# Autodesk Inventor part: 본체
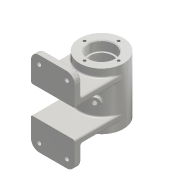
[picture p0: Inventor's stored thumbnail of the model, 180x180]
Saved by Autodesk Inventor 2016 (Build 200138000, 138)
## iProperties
Created: 2017-02
Part Number: 본체
Material: 알루미늄 6061
Document SubType Name: Modeling
Designer: H
Density: 2.7 g/cm^3
Appearance: 알루미늄 - 평지
Mass: 354.506 g
Surface Area: 423.343 cm^2
Volume: 131.299 cm^3
Author: H
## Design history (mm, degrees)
sketch "스케치1"
  geometry: L1 (0, 0)-(0, -48.036); L2 (0, 0)-(27, 0); L3 (27, 35)-(0, 35); L4 (0, 35)-(0, -35); L5 (0, -35)-(27, -35); L6 (27, -35)-(27, 35); L7 (0, -10)-(27, -10); L8 (32, -5)-(21.317, -5); L9 (21.317, -5)-(21.317, -10); L10 (21.317, -10)-(32, -10); L11 (32, -10)-(32, -5)
  constraints: 22 end point, 4 horizontal, 4 parallel, 4 point on line, 2 perpendicular, 1 vertical, 1 other
  dimensions: "d0" = 54 diameter of L6 L1; "d1" = 48.03642 distance of L1.start L1.end; "d2" = 27 distance of L1.start L2.end; "d4" = 70 distance of L5.end L3.start; "d5" = 5 distance of L10.end L8.start; "d6" = 10.68275 distance of L8.start L8.end; "d7" = 5 distance between parallel lines of L6 L11; "d109" = 25 distance between parallel lines of L5 L10
revolve "회전1" stored, may be unused: angle "d8" = 90 deg
revolve "회전2" stored, may be unused: angle "d9" = 90 deg
sketch "스케치2"
  geometry: L1 (-52, 52)-(-60, 52); L2 (-60, 52)-(-60, 17); L3 (-60, 17)-(-52, 17); L4 (-52, 17)-(-52, 52); L5 (0, 0)-(-22.662, 0); L6 (-52, 17)-(-2, 17); L7 (-2, 17)-(-2, 25); L8 (-2, 25)-(-52, 25); L9 (-52, 25)-(-52, 17)
  constraints: 18 end point, 4 parallel, 3 horizontal, 2 perpendicular
  dimensions: "d10" = 22.66207 distance of L5.start L5.end; "d11" = 52 distance between parallel lines of L5 L1; "d12" = 8 distance of L1.start L1.end; "d13" = 17 distance between parallel lines of L5 L3; "d14" = 60 distance from line of L5.start L2; "d15" = 50 distance of L7.end L8.end; "d16" = 8 distance of L6.end L7.end
extrude "돌출1" join sketch "스케치2" stored distance "d17" = 54; taper "d18" = 0 deg
sketch "스케치3"
  geometry: 2 further points
  constraints: 1 coincident
hole "구멍1" sketch "스케치3" at (0, 0) diameter "d19" = 32; stored, may be unused: countersink angle "d23" = 90 deg, drill point angle "d25" = 0 deg; dims "d20" = 6, "d21" = 4, "d22" = 2, "d24" = 12
sketch "스케치4"
  geometry: 2 further points
  constraints: 1 coincident
hole "구멍2" sketch "스케치4" at (0, 0) diameter "d26" = 28; stored, may be unused: countersink angle "d30" = 90 deg, drill point angle "d32" = 0 deg; dims "d27" = 6, "d28" = 4, "d29" = 2, "d31" = 3
sketch "스케치5"
  geometry: 2 further points
  constraints: 1 coincident
hole "구멍3" sketch "스케치5" at (0, 0) diameter "d33" = 44; stored, may be unused: countersink angle "d37" = 90 deg, drill point angle "d39" = 0 deg; dims "d34" = 6, "d35" = 4, "d36" = 2, "d38" = 40
sketch "스케치6"
  geometry: C1 r 5 at (0, 0) reference; 2 further points
  constraints: 1 coincident
hole "구멍4" sketch "스케치6" at (0, 0) diameter "d40" = 5.188; stored, may be unused: countersink angle "d44" = 90 deg, drill point angle "d46" = 0 deg; dims "d41" = 12, "d42" = 4, "d43" = 2, "d45" = 23.25
sketch "스케치8" dims "d47" = 9
  geometry: L1 (14.5, 14.402)-(10, 11.804); L2 (10, 11.804)-(5.5, 14.402); L3 (5.5, 14.402)-(5.5, 19.598); L4 (5.5, 19.598)-(10, 22.196); L5 (10, 22.196)-(14.5, 19.598); L6 (14.5, 19.598)-(14.5, 14.402); L7 (0, -8)-(0, 27) reference; 4 further points
  constraints: 12 end point, 1 coincident, 1 horizontal alignment, 1 midpoint, 1 parallel, 15 other
  dimensions: "d48" = 17 horizontal distance of point (10, 17) point (27, -25); "d49" = 42 vertical distance of point (27, -25) point (10, 17)
extrude "돌출2" cut sketch "스케치8" distance "d50" = 3; taper "d51" = 0 deg
sketch "스케치9"
  geometry: 2 further points
  dimensions: "d52" = 42 vertical distance of point (10, 17) point (27, -25); "d53" = 17 horizontal distance of point (27, -25) point (10, 17)
hole "구멍5" sketch "스케치9" at (10, 17) diameter "d54" = 5; stored, may be unused: countersink angle "d58" = 90 deg, drill point angle "d60" = 0 deg; dims "d55" = 12, "d56" = 4, "d57" = 2, "d59" = 23.25
sketch "스케치10"
  geometry: L1 (5, 32)-(-5, 32) reference; L2 (0, 0)-(0, 32); 1 further point
  constraints: 2 end point, 1 midpoint, 1 point on line
  dimensions: "d67" = 21 distance of L2.start point (0, 21)
hole "구멍6" sketch "스케치10" at (0, 21) diameter "d68" = 3.459; stored, may be unused: countersink angle "d72" = 90 deg, drill point angle "d74" = 118 deg; dims "d69" = 8, "d70" = 4, "d71" = 2, "d73" = 10
fillet "모깎기2" dims "d79" = 10
fillet "모깎기3" dims "d80" = 2
fillet "모깎기4" dims "d81" = 2
fillet "모깎기5" dims "d82" = 2
fillet "모깎기6" dims "d83" = 2
fillet "모깎기7" dims "d84" = 2
fillet "모깎기8" dims "d85" = 2
fillet "모깎기9" dims "d86" = 2
chamfer "모따기1" distance "d87" = 1; stored, may be unused: second distance "d88" = 2, angle "d89" = 45 deg
fillet "모깎기10" dims "d90" = 0.3
fillet "모깎기11" dims "d91" = 3
sketch "스케치11"
  geometry: L1 (0, 0)-(14.705, -22.644); L2 (0, 0)-(0, -27); L3 (12.458, -19.184)-(16.339, -25.16); L4 (16.339, -25.16)-(21.371, -21.892); L5 (21.371, -21.892)-(17.49, -15.916); L6 (17.49, -15.916)-(12.458, -19.184); A1 r 27 centre (0, 0) between (-23.276, -13.683) and (23.276, -13.683) reference; 1 further point
  constraints: 12 end point, 2 parallel, 2 point on circle, 2 point on line, 1 perpendicular
  dimensions: "d92" = 33 deg angle of L2 L1; "d93" = 30 distance from line of point (0, 0) L4; "d94" = 6 distance from line of L3 L4.end; "d95" = 5.97589 vertical distance of L4.end L5.end
revolve "회전3" sketch "스케치11" stored, may be unused: angle "d96" = 90 deg
sketch "스케치13"
  geometry: 2 further points
  constraints: 1 coincident
hole "구멍7" sketch "스케치13" at (0, 0) diameter "d97" = 5.188; stored, may be unused: countersink angle "d101" = 90 deg, drill point angle "d103" = 118 deg; dims "d98" = 17.5, "d99" = 4, "d100" = 2, "d102" = 17.5
fillet "모깎기12" dims "d104" = 2
node "작업 평면2"
sketch "스케치14"
  geometry: L1 (0, 57.5)-(0, -12.5) reference; L2 (54, -19.5)-(54, -4.5) reference; L3 (60, -19.5)-(54, -19.5) reference; L4 (60, 3.5)-(60, -19.5) reference; L5 (2, 3.5)-(60, 3.5) reference; L6 (2, -0.5)-(2, 3.5) reference; L7 (50, -0.5)-(2, -0.5) reference; L8 (50, 45.5)-(2, 45.5) reference; L9 (2, 41.5)-(2, 45.5) reference; L10 (2, 41.5)-(60, 41.5) reference; L11 (60, 64.5)-(60, 41.5) reference; L12 (60, 64.5)-(54, 64.5) reference; L13 (54, 64.5)-(54, 49.5) reference; L14 (-27, -12.5)-(27, -12.5) reference; L15 (27, 57.5)-(27, -12.5) reference; A1 r 4 centre (50, -4.5) between (50, -0.5) and (54, -4.5) reference; A2 r 4 centre (50, 49.5) between (54, 49.5) and (50, 45.5) reference; 2 further points
  constraints: 1 other
  dimensions: "d105" = 35 distance from line of L14 point (0, 22.5); "d106" = 27 distance from line of L15 point (0, 22.5)
feature "엠보싱1" sketch "스케치14" dims "d0" = 54, "d1" = 48.03642, "d2" = 27, "d4" = 70, "d5" = 5, "d6" = 10.68275, "d7" = 5, "d10" = 22.66207, "d11" = 52, "d12" = 8, "d13" = 17, "d14" = 60, "d15" = 50, "d16" = 8, "d107" = 0.5, "d108" = 0, "d109" = 25
node "솔리드1"
mirror "대칭1"
mirror "대칭2"
pattern_linear "직사각형 패턴1" dims "d63" = 34, "d66" = 84
pattern_circular "원형 패턴1" dims angle "d76" = 360 deg
mirror "대칭3"
node "절단 모서리 투영1"
